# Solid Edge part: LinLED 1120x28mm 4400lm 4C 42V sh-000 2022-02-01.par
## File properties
Author: jaroslaw.przewlocki
Template: iso metric part.par
Last saved by: jaroslaw.przewlocki
Revision: 12
Application: Solid Edge
Gęstość: 0,000 kg/m^3
Dokładność: 0,990
Username: jaroslaw.przewlocki
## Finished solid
Body 1: solid body, 5448 faces, 16976 edges, 11528 vertices.
  Faces by surface: plane 3458, cylinder 1670, spline 192, cone 60, sphere 32, torus 20, spun 16
  Edges by curve: line 11468, circle 3164, curve on surface 2104, ellipse 132, spline 100, intersection 8
Bounding box of the edges (mm; curved faces can reach further): 1119.000 x 5.050 x 28.000, from (-559.5, -3.45, -14) to (559.5, 1.6, 14).
Cylindrical faces by radius (mm): R0.1 x896, R0.2 x540, R0.2169 x12, R0.25 x24, R0.3373 x12, R0.4 x16, R0.4006 x4, R0.4008 x4, R0.525 x4, R0.6 x40, R1 x16, R1.05 x39, R1.1 x8, R1.2 x20, R1.8 x35
Conical faces (half-angle, radius in mm at the cone's reference point): 0.5 deg R0.5056 x8, 0.5 deg R1.0082 x8, 1 deg R0.5511 x4, 10 deg R0.2132 x8, 10 deg R0.4132 x8, 18.8604 deg R1.0669 x8, 27.363 deg R0.6214 x4, 45 deg R0.575 x4, 45 deg R0.625 x8
Toroidal faces (ring radius, tube radius in mm): R0.8 r0.2 x8, R0.8522 r0.3 x4, R0.9002 r0.2 x4, R0.9018 r0.2 x4
Spherical faces by radius (mm): R0.2 x24, R0.6 x8
Planar faces by outward normal: +x 561, +y 129, +z 503, -x 393, -y 497, -z 503, oblique 872
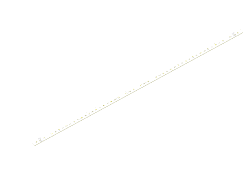
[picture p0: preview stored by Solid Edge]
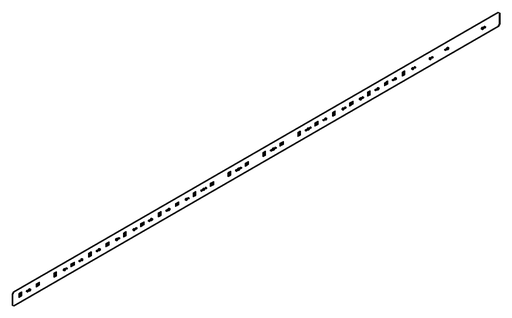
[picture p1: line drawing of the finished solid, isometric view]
